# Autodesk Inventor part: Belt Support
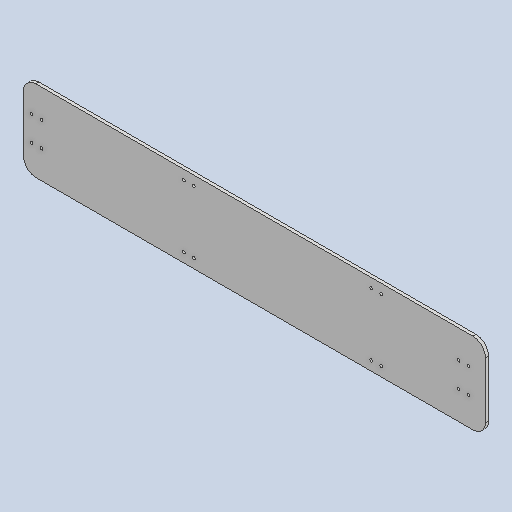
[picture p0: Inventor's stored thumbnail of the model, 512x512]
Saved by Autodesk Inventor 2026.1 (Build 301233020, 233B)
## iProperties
Created: 2026-10
Part Number: Belt Support
Material: Generic
Document SubType Name: Modeling
Designer: hp
Density: 1 g/cm^3
Appearance: Default
Author: hp
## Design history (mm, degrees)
sketch "Sketch1"
  geometry: L1 (0, 0)-(740, 0); L2 (740, 0)-(740, 130); L3 (740, 130)-(0, 130); L4 (0, 130)-(0, 0)
  constraints: 8 end point, 2 parallel, 1 horizontal, 1 perpendicular
  dimensions: "d0" = 740 distance of L3.end L2.end; "d1" = 130 distance of L2.end L1.end
extrude "Extrusion1" new body sketch "Sketch1" distance "d2" = 5; taper "d3" = 0 deg
fillet "Fillet1" dims "d4" = 20
sketch "Sketch2"
  geometry: 8 further points
hole "Hole1" sketch "Sketch2" at (-713, 85), (-697, 85), (-713, 45), (-697, 45), (-29, 85), (-29, 45), (-13, 45), (-13, 85) diameter "d5" = 4.5; stored, may be unused: countersink angle "d9" = 90 deg, drill point angle "d11" = 0 deg; dims "d6" = 6, "d7" = 4, "d8" = 2, "d10" = 8
sketch "Sketch3"
  geometry: 8 further points
hole "Hole2" sketch "Sketch3" at (573, 15), (557, 15), (273, 15), (257, 15), (573, 115), (557, 115), (273, 115), (257, 115) diameter "d12" = 4.5; stored, may be unused: countersink angle "d16" = 90 deg, drill point angle "d18" = 0 deg; dims "d13" = 6, "d14" = 4, "d15" = 2, "d17" = 8
body "Solid1"
